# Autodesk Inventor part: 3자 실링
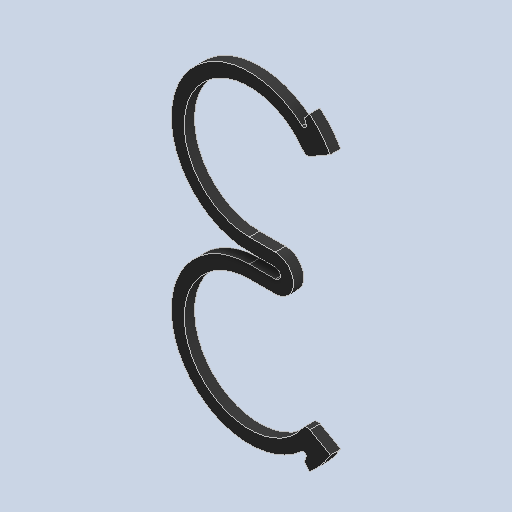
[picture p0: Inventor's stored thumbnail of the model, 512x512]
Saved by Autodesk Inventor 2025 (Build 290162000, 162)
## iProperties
Created: 2026-08
Part Number: 3자 실링
Material: 고무
Document SubType Name: Modeling
Designer: KDI
Density: 0.93 g/cm^3
Appearance: 기본값
Author: jhkim
Sending System: Autodesk Inventor 2027
Preprocessor: ST-DEVELOPER v20.1
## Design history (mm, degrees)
feature "솔리드1"
node "솔리드2"
